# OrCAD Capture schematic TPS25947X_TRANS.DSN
size E; title: TPS25947x: 2.7 - 23 V, 5.5 A, 28 mÙ True Reverse Current; rev: 1.0; note: Datasheet: SLVSFC9     EVM: SLVUC01; note: Blocking eFuse with Input Reverse Polarity Protection
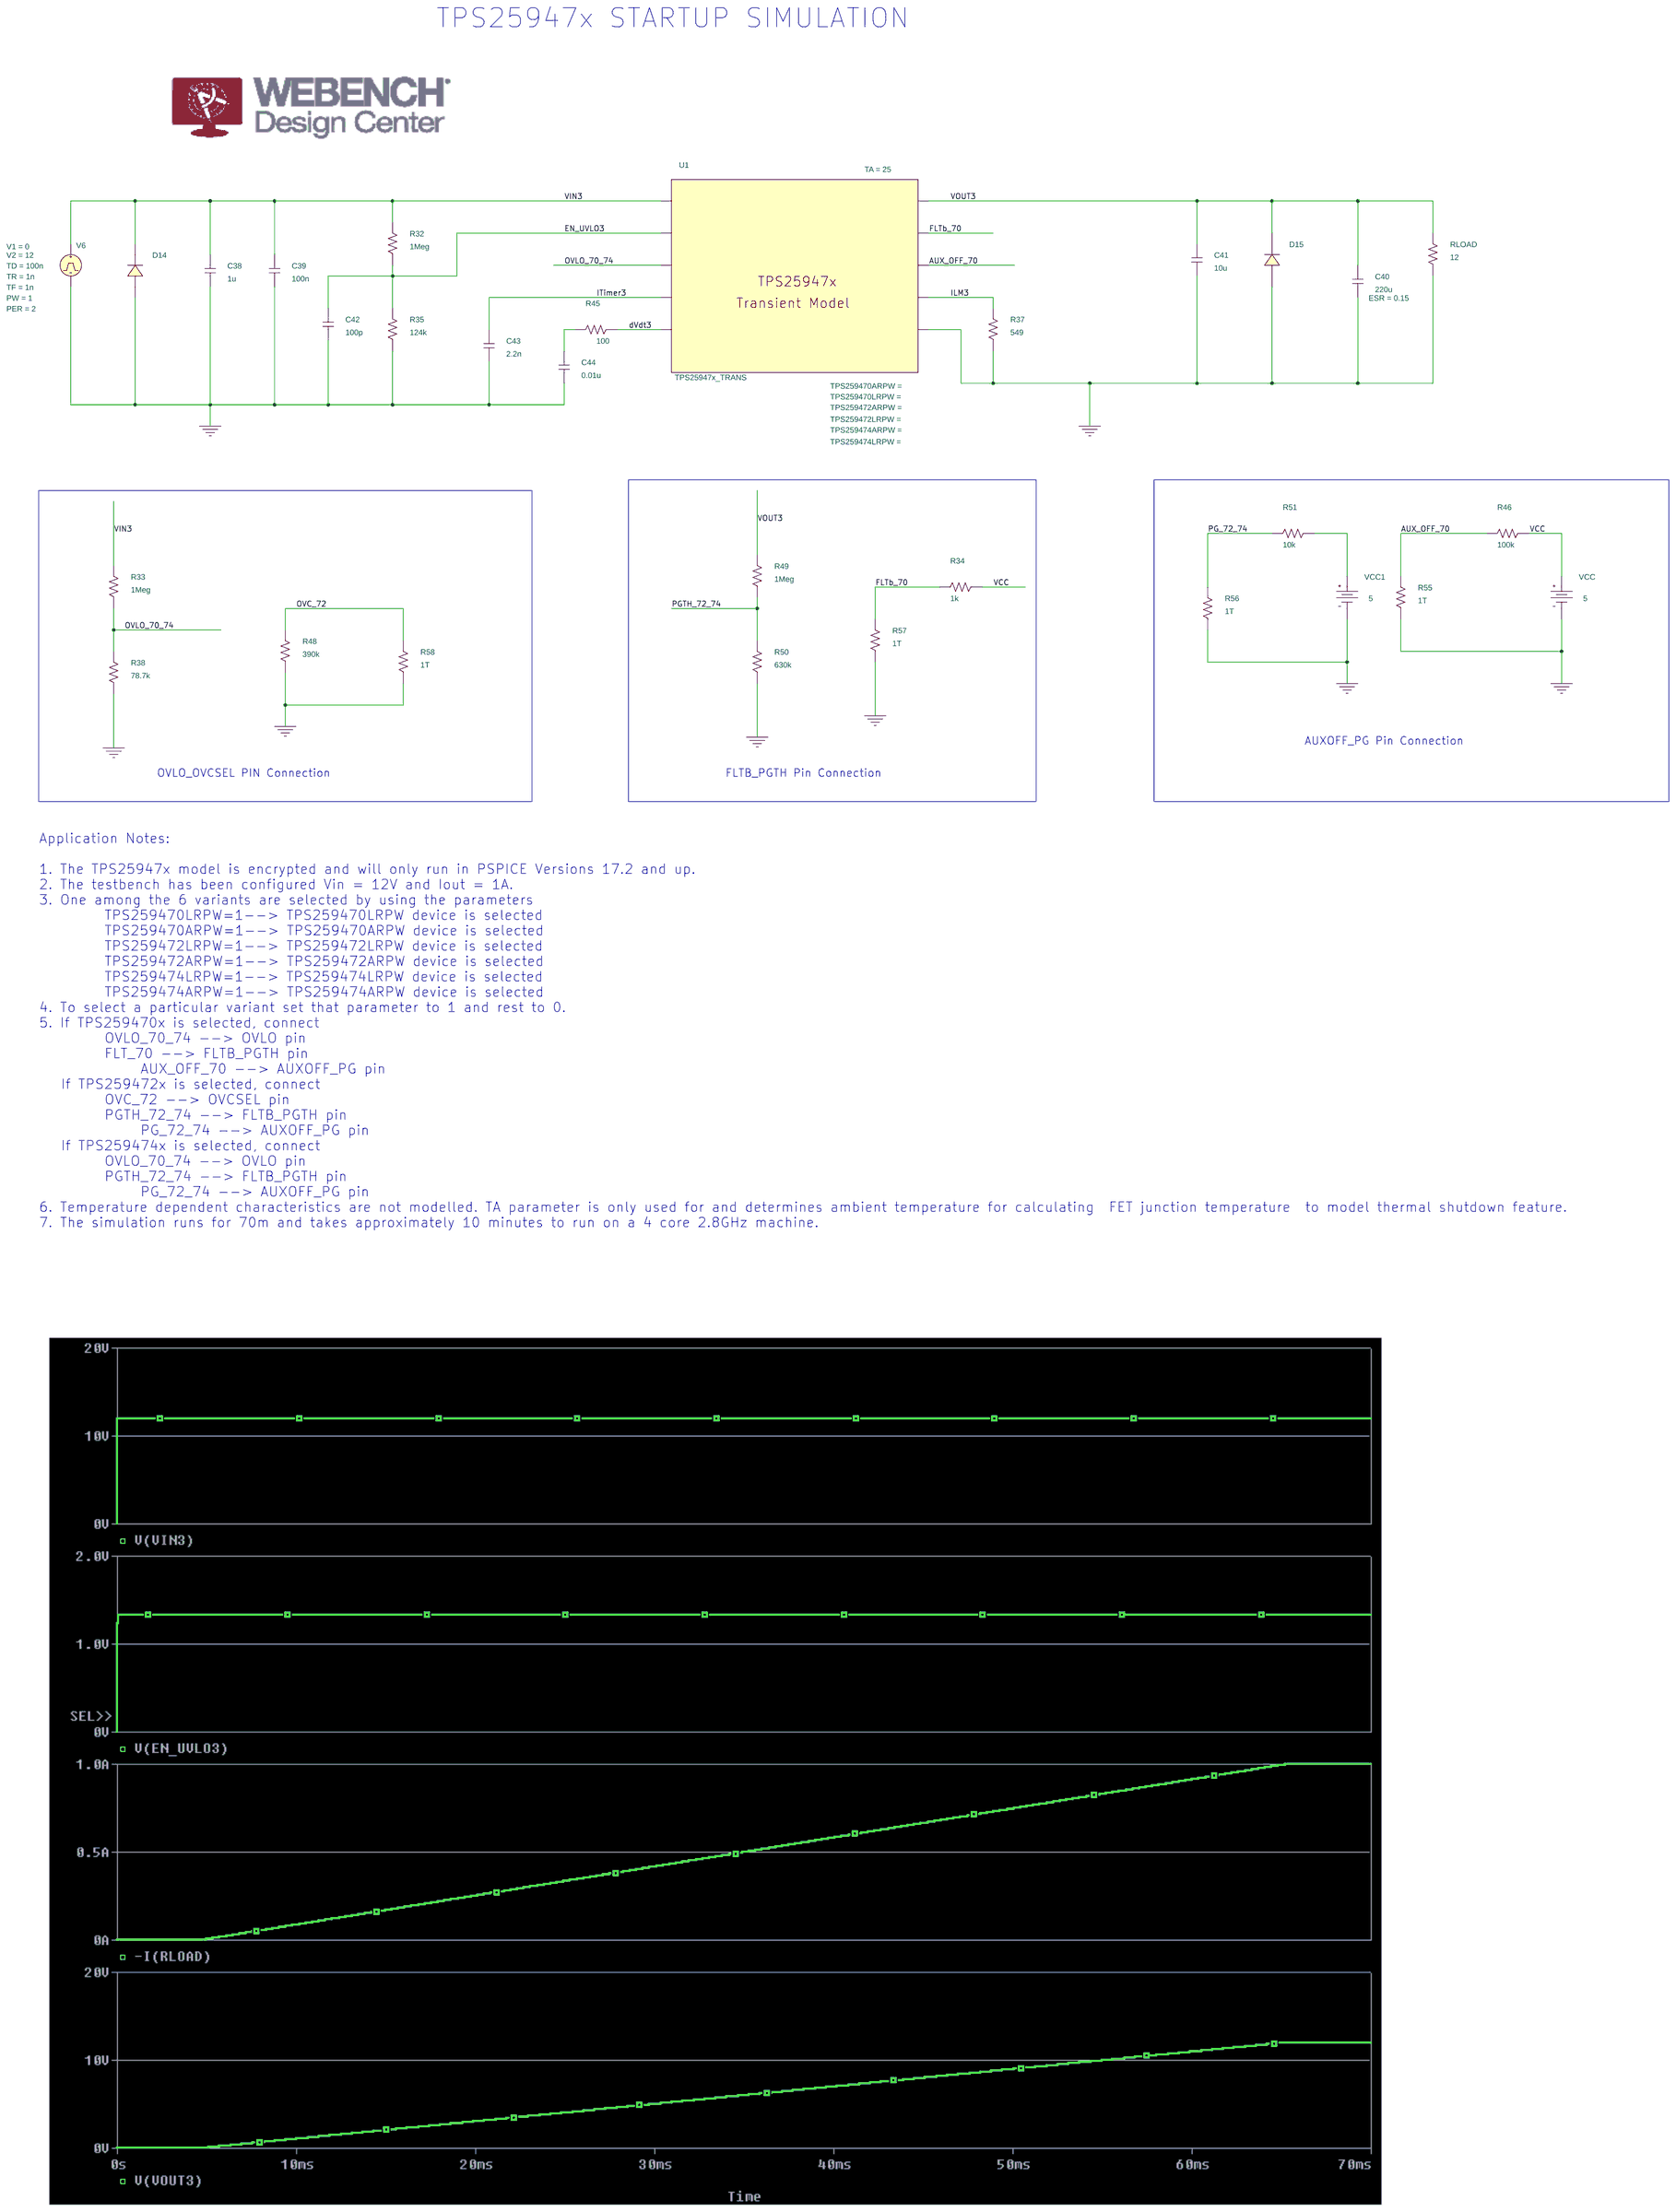
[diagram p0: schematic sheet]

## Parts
C38  1u  [RAD/CK05]
C39  100n  [RAD/CK05]
C40  220u  [RAD/CK05]
C41  10u  [RAD/CK05]
C42  100p  [RAD/CK05]
C43  2.2n  [RAD/CK05]
C44  0.01u  [RAD/CK05]
D14  SMBJ18A
D15  B330A
R32  1Meg  [AX/RC05]
R33  1Meg  [AX/RC05]
R34  1k  [AX/RC05]
R35  124k  [AX/RC05]
R37  549  [AX/RC05]
R38  78.7k  [AX/RC05]
R45  100  [AX/RC05]
R46  100k  [AX/RC05]
R48  390k  [AX/RC05]
R49  1Meg  [AX/RC05]
R50  630k  [AX/RC05]
R51  10k  [AX/RC05]
R55  1T  [AX/RC05]
R56  1T  [AX/RC05]
R57  1T  [AX/RC05]
R58  1T  [AX/RC05]
RLOAD  12  [AX/RC05]
U1  TPS25947x_TRANS
V6  VPULSE
VCC  VDC
VCC1  VDC

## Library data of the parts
C38 C39 C41-C44 = C
C40 = C: AppProp: InductiveSlave:;SRF:;PrevCap:220u;PrevESL:; ESR: 0.15
D14 = D_D1: PSpiceTemplate: X^@REFDES  %C %A @MODEL
D15 = D_D1: PSpiceTemplate: D^@REFDES  %A %C @MODEL ?AREA/@AREA/
R32-R35 R37 R38 R45 R46 R48-R51 R55-R58 RLOAD = R
U1 = TPS25947x_TRANS: TA: 25
V6 = VPULSE: PER: 2; PW: 1; TD: 100n; TF: 1n; TR: 1n; V1: 0; V2: 12
VCC VCC1 = VDC: DC: 5

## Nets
VCC: R34.1 R46.1 VCC.0(+)
VIN3: C38.2 C39.2 D14.1(C) R32.2 R33.2 U1.IN V6.1(+)
0: C38.1 C39.1 C40.1 C41.1 C42.1 C43.1 C44.1 D14.2(A) D15.2(A) R35.1 R37.1 R38.1 R48.1 R50.1 R55.1 R56.1 R57.1 R58.1 RLOAD.1 U1.GND V6.2(-) VCC.1(-) VCC1.1(-)
AUX_OFF_70: R46.2 R55.2 U1.AUXOFF_PG
dVdt3: R45.1 U1.DVDT
EN_UVLO3: C42.2 R32.1 R35.2 U1.EN_UVLO
FLTb_70: R34.2 R57.2 U1.FLTB_PGTH
ILM3: R37.2 U1.ILM
ITimer3: C43.2 U1.ITIMER
OVC_72: R48.2 R58.2
OVLO_70_74: R33.1 R38.2 U1.OVLO_OVCSEL
PG_72_74: R51.2 R56.2
PGTH_72_74: R49.1 R50.2
VOUT3: C40.2 C41.2 D15.1(C) R49.2 RLOAD.2 U1.OUT
N21460: C44.2 R45.2
N41060: R51.1 VCC1.0(+)

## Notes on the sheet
- TPS25947x STARTUP SIMULATION
- AUXOFF_PG Pin Connection
- OVLO_OVCSEL PIN Connection
- FLTB_PGTH Pin Connection
- Application Notes:
  1. The TPS25947x model is encrypted and will only run in PSPICE Versions 17.2 and up.
  2. The testbench has been configured Vin = 12V and Iout = 1A.
  3. One among the 6 variants are selected by using the parameters
           TPS259470LRPW=1--> TPS259470LRPW device is selected
           TPS259470ARPW=1--> TPS259470ARPW device is selected
           TPS259472LRPW=1--> TPS259472LRPW device is selected
           TPS259472ARPW=1--> TPS259472ARPW device is selected
           TPS259474LRPW=1--> TPS259474LRPW device is selected
           TPS259474ARPW=1--> TPS259474ARPW device is selected
  4. To select a particular variant set that parameter to 1 and rest to 0.
  5. If TPS259470x is selected, connect
           OVLO_70_74 --> OVLO pin
           FLT_70 --> FLTB_PGTH pin
  	         AUX_OFF_70 --> AUXOFF_PG pin
     If TPS259472x is selected, connect
           OVC_72 --> OVCSEL pin
           PGTH_72_74 --> FLTB_PGTH pin
  	         PG_72_74 --> AUXOFF_PG pin
     If TPS259474x is selected, connect
           OVLO_70_74 --> OVLO pin
           PGTH_72_74 --> FLTB_PGTH pin
  	         PG_72_74 --> AUXOFF_PG pin
  6. Temperature dependent characteristics are not modelled. TA parameter is only used for and determines ambient temperature for calculating  FET junction temperature  to model thermal shutdown feature.
  7. The simulation runs for 70m and takes approximately 10 minutes to run on a 4 core 2.8GHz machine.
